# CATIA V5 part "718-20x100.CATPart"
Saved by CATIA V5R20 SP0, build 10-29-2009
Part number: 718-20x100
Definition: NONE
Nomenclature: 718-20x100
Source: Unknown
Description: 718-20x100
Bounding box of the stored display mesh (mm): x 0 to 123, y -12.5 to 12.5, z -12.5 to 12.5
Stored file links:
  C:\Users\Utente\Desktop\IO LAVORO\3D X SITO CF\X SITO\718\718-20x100.CATPart
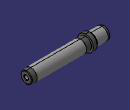
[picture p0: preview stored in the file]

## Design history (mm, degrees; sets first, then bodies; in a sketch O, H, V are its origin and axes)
Body1 "718-20x100" (main body)
  Solid1: solid without history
